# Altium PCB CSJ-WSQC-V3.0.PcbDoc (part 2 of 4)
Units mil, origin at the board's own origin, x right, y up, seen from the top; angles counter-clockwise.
Board outline 5060 x 7131.55 mil, 4 copper layers (Top Layer, InternalPlane1, InternalPlane2, Bottom Layer); 390 components, 277 nets, 1183 pads, 601 vias.
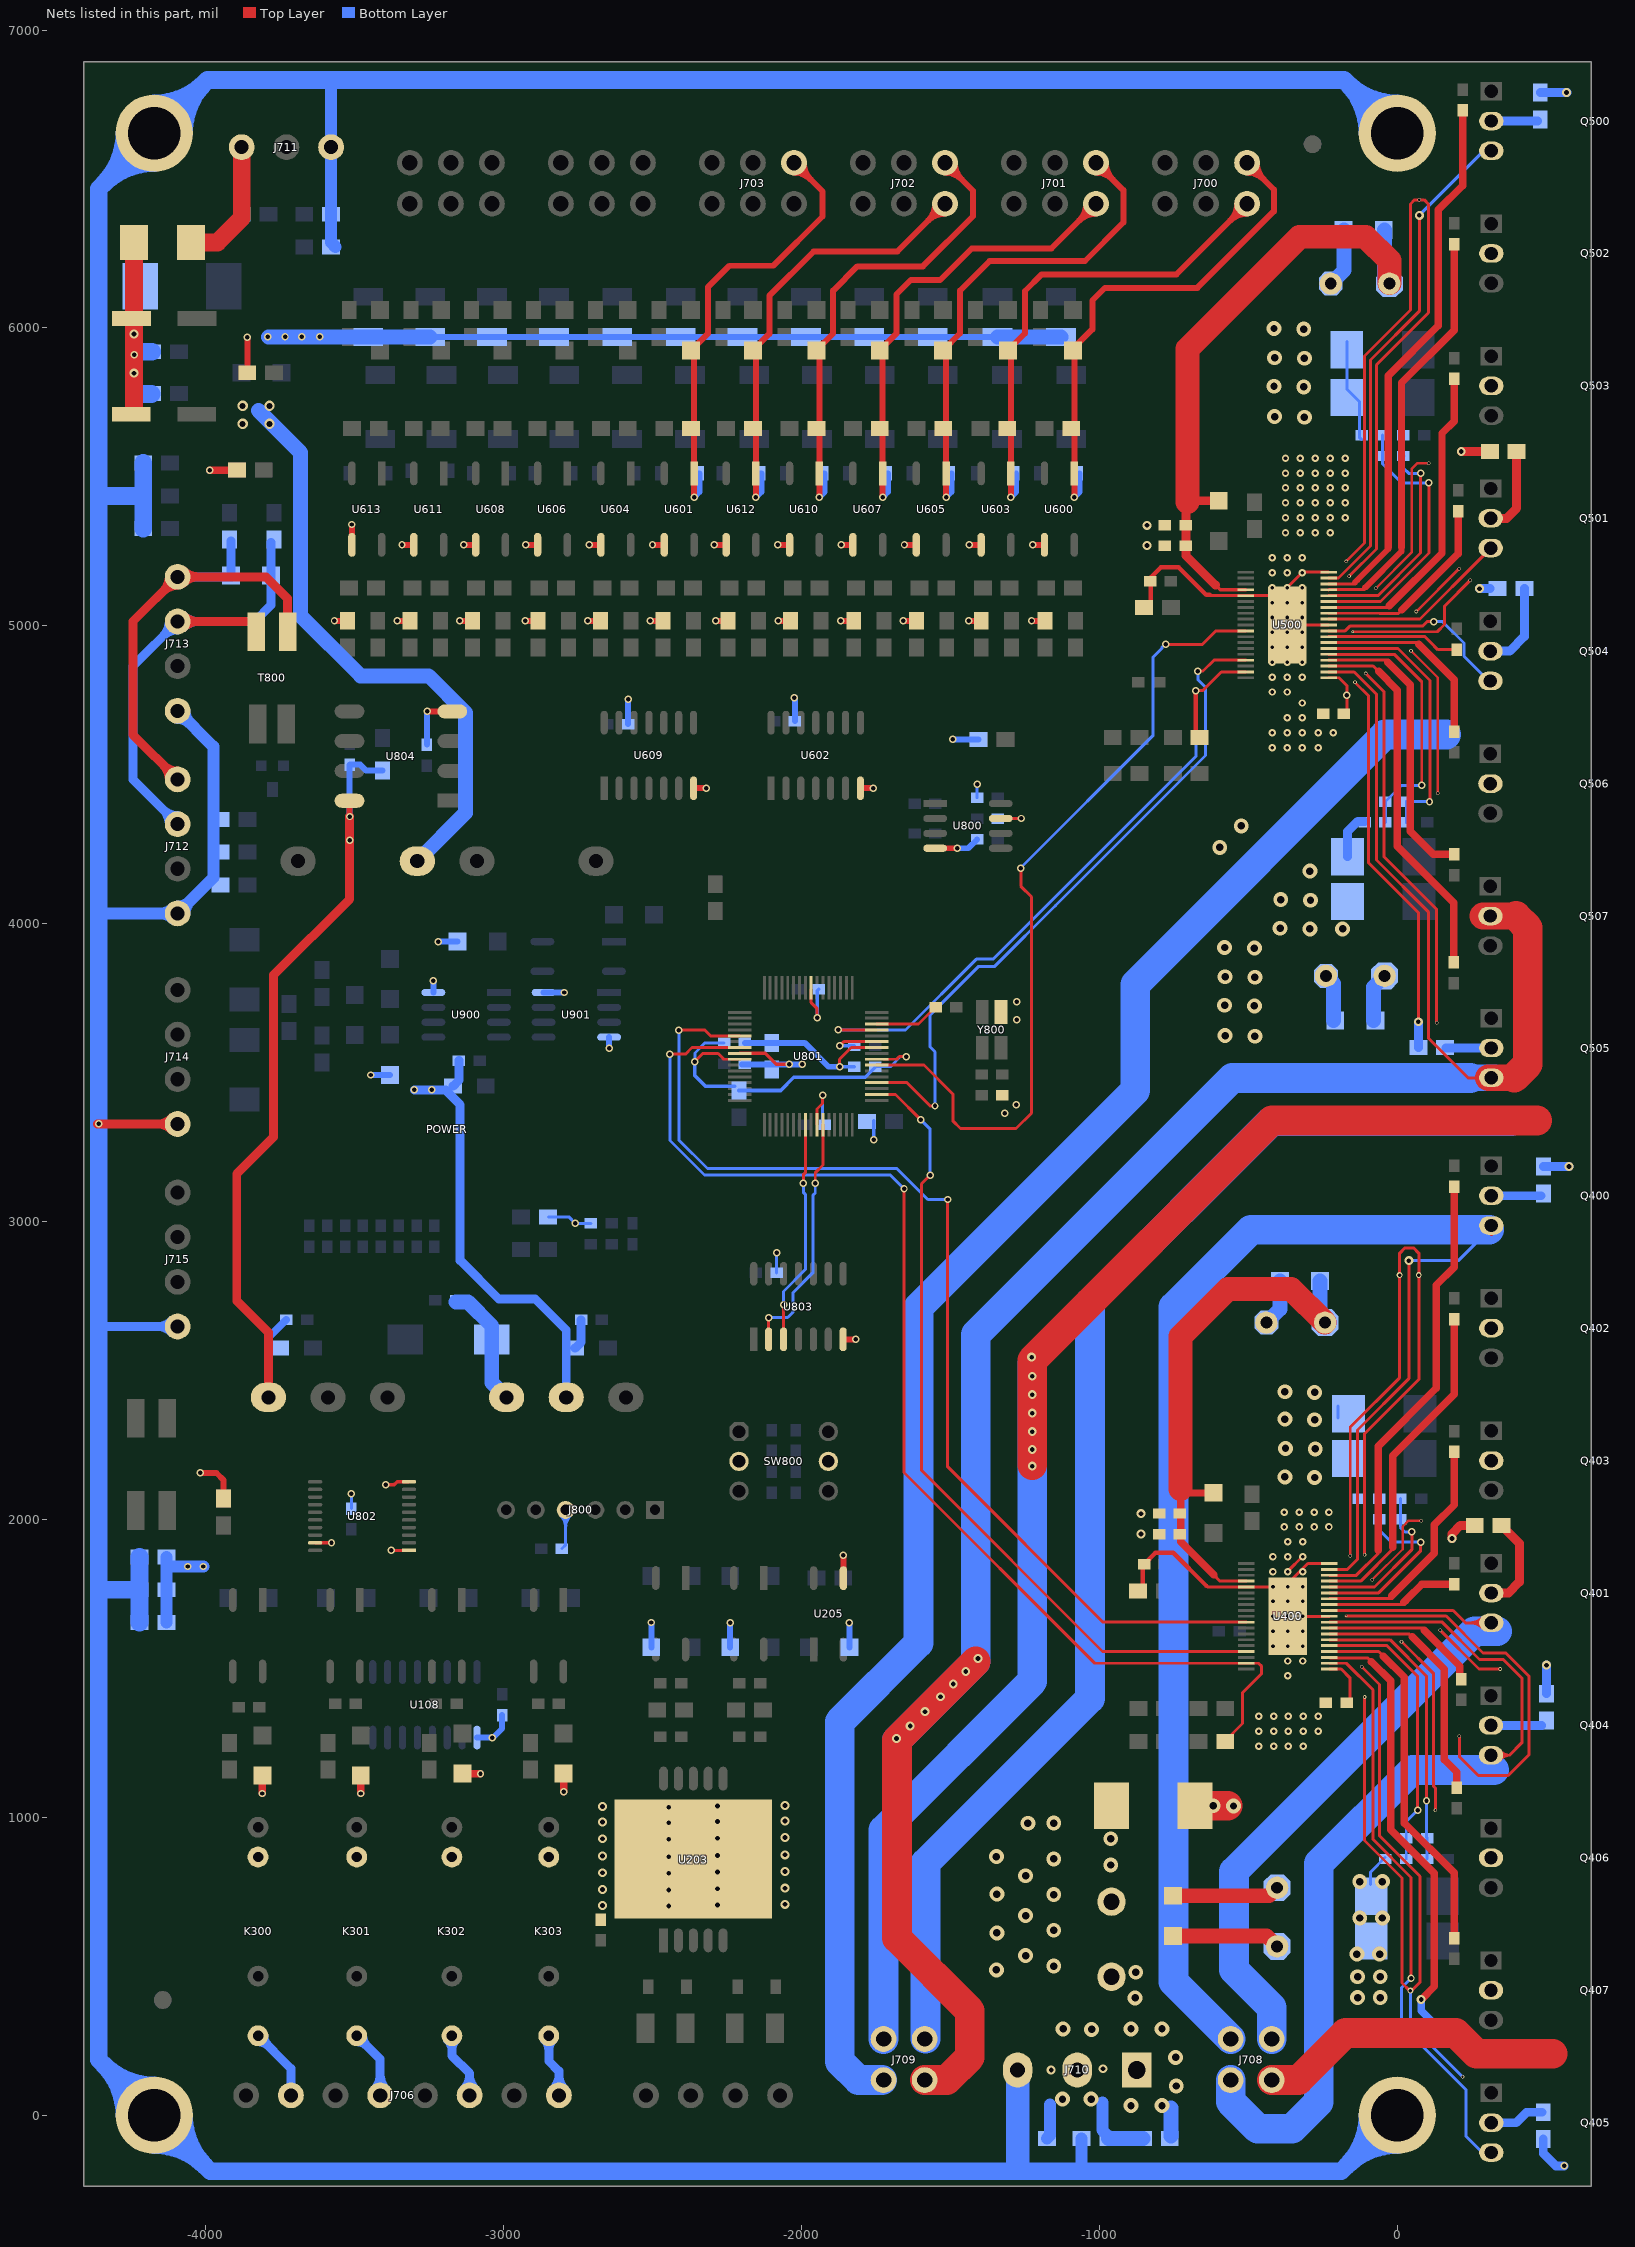
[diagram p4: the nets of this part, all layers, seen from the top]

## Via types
v1: diameter 25, hole 15, Top Layer to Bottom Layer, 303 vias
v2: diameter 25, hole 12, Top Layer to Bottom Layer, 94 vias
v3: diameter 50, hole 25, Top Layer to Bottom Layer, 71 vias
v4: diameter 30, hole 16, Top Layer to Bottom Layer, 71 vias
v5: diameter 12, hole 8, Top Layer to Bottom Layer, 25 vias
v6: diameter 25, hole 12, Top Layer to Bottom Layer, tented both sides, 24 vias
v7: diameter 35, hole 20, Top Layer to Bottom Layer, 7 vias
v8: diameter 20, hole 12, Top Layer to Bottom Layer, 3 vias
v9: diameter 8, hole 5, Top Layer to Bottom Layer, 2 vias
v10: diameter 35, hole 25, Top Layer to Bottom Layer, 1 vias

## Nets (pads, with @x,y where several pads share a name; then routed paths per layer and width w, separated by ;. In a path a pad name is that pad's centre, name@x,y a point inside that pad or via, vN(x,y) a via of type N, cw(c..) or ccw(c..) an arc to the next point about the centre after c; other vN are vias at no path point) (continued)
485P1: C116.1 C117.1 C119.1 C120.1 D105.1 POWER.6 R901.2 R902.1 U900.8 U901.8 | length 1958.1
  Top Layer w20: v1(-4018,2156) -3964,2156 -3940,2132 D105.1@-3940,2070
  Bottom Layer w20: v1(-3446,3492) R902.1@-3382,3492 ; U900.8@-3236,3769 v1(-3236,3808) ; v1(-3219,3940) R901.2@-3155,3940 ; U901.8@-2866,3769 v1(-2797,3769)
  Bottom Layer w30: v1(-3300,3442) -3196,3442 -3146,3392 -3146,2870 -3016,2740 -2894,2740 -2790,2636 POWER.6@-2790,2410 ; C120.1@-3170,3455 -3150,3475 C119.1@-3150,3540 ; C117.1@-2760,2575 -2740,2595 C116.1@-2740,2670
  other v1: -3242,3442
+5V: C108.1 C109.1 C808.1 C816.1 D101.1 POWER.10 U804.8 | length 2871.6
  Top Layer w20: v1(-3517.45,4359.73) U804.8@-3517.45,4412.73
  Top Layer w25: v1(-3986,5522.44) D101.1@-3895.38,5522.44
  Top Layer w30: POWER.10@-3790,2410 -3790,2628 -3896,2734 -3896,3160 -3772,3284 -3772,3828 -3517.45,4082.55 v1(-3517.45,4359.73)
  Bottom Layer w20: v1(-3517.45,4359.73) -3517.45,4532.73 C808.1@-3516.45,4533.73 -3481.45,4533.73 -3461.45,4513.73 C816.1@-3406.45,4513.73
  Bottom Layer w25: POWER.10@-3790,2410 -3790,2610 C108.1@-3730,2670
  other v1: -3517.45,4280
+24V: C101.1 C102.1 C104.1 C105.1 C201.1 C304.1 D100.2 D103.1 F100.2 K300.3 K301.3 K302.3 K303.3 POWER.2 R200.1 R204.1 R221.2 R300.1 R305.1 R313.1 R319.1 R700.2 R701.2 R702.2 R703.2 R704.2 R705.2 R706.2 R707.2 R708.2 R709.2 R710.2 R711.2 U108.9 U203.11 | length 6446.9
  Top Layer w20: D103.1@-3860.73,5849.38 v1(-3860.73,5968.73)
  Top Layer w25: v1(-3810,1080) R319.1@-3810,1140 ; v1(-3480,1080) R313.1@-3480,1140 ; R305.1@-3137.78,1146.73 v1(-3077.78,1146.73) ; v1(-2798,1086) R300.1@-2798,1146
  Top Layer w60: C102.1@-4240.79,5719.21 v4(-4240.79,5848) F100.2@-4240.79,6286.73
  Bottom Layer w20: R711.2@-3246.72,5969.73 R704.2@-3038.99,5969.73 R710.2@-2831.27,5969.73 R703.2@-2618.54,5969.73 R709.2@-2405.81,5969.73 R702.2@-2198.08,5969.73 R708.2@-1985.36,5969.73 R701.2@-1772.63,5969.73 R707.2@-1559.9,5969.73 R700.2@-1342.18,5969.73 ; U108.9@-3089.45,1267.73 v1(-3038,1267.73) ; v1@-3035.45,1267.73 -3005.45,1297.73 C304.1@-3005.45,1342.73 ; R200.1@-2504.45,1570.73 v1@-2504.45,1653.55 ; R204.1@-2239.45,1570.73 v1(-2239.45,1653.55) ; R221.2@-1839.45,1570.73 v1(-1839.45,1653.55)
  Bottom Layer w50: -3823,5723 -3682,5582 -3682,5034 -3480,4832 -3252,4832 -3128,4708 -3128,4372 POWER.2@-3290,4210 ; v1@-3790,5969.73 R705.2@-3454.45,5969.73 R711.2@-3246.72,5969.73 ; R700.2@-1342.18,5969.73 R706.2@-1129.45,5969.73
  Bottom Layer w60: D100.2@-4240.79,6133.07 v4(-4240.79,5980) v4(-4240.79,5848) -4240.79,5778 C105.1@-4182,5778 ; v1@-4236.79,5920 C104.1@-4180,5920
  other v1: -2504,1654 -4240.79,5910 -3792,5970 -3734,5969.73 -3678,5970 -3618,5970
  other v4: -2446,702 -2668,704 -2282,706 -2056,708 -2446,756 -2668,758 -2282,760 -2056,762 -2446,812 -2668,814 -2282,816 -2056,818 -2446,868 -2668,870 -2282,872 -2056,874 -2446,926 -2668,928 -2282,930 -2056,932 -2446,982 -2668,984 -2282,986 -2056,988 -2446,1034 -2668,1036 -2282,1038 -2056,1040
  other v7: -3876,5678 -3786,5678 -3876,5738 -3786,5738
+24VIN: C100.1 F100.1 J711.3 | length 667.1
  Top Layer w60: F100.1@-4049.45,6286.73 -3961.27,6286.73 -3879.45,6368.55 J711.3@-3879.45,6606.73
  Bottom Layer w50: C100.1@-3879.45,6381.73 J711.3@-3879.45,6606.73
+48V: C400.1 C401.1 C402.1 C403.1 C404.1 C405.1 C407.2 C410.1 C411.1 C413.1 C414.1 C500.1 C501.1 C502.1 C503.1 C504.1 C505.1 C507.2 C510.1 C511.1 C513.1 C514.1 D104.2 pad.@-26.6,6148.73 pad.@-42.6,3824.73 pad.@-242.6,2660.73 pad.@-403.45,763.58 Q400.2 Q401.2 Q404.2 Q405.2 Q500.2 Q501.2 Q504.2 Q505.2 R111.2 U400.4 U500.4 | length 6283.8
  Top Layer w10: -616,1814 -594.84,1792.84 U400.4@-506.62,1792.84
  Top Layer w12: -619.15,5145.15 -611,5137 -594.84,5120.84 U500.4@-508.62,5120.84
  Top Layer w20: C407.2@-608.45,2089.73 C407.2@-607.45,2089.73 ; C401.1@-243.45,2660.73 C401.1@-242.6,2660.73
  Top Layer w25: -727.45,2102 -727.45,2088.73 ; -616,1814 -616.49,1814 -727.45,1924.96 -727.45,2088.73 ; C407.2@-608.45,2088.73 -727.45,2088.73 ; C401.1@-243.02,2660.31 C401.1@-242.6,2660.73
  Top Layer w30: -709.45,5415.45 -709.45,5235.45 -611,5137 ; -709.45,5440.55 -704,5446 ; -688.63,5419.73 C507.2@-599.45,5419.73 ; C513.1@-26.6,6133.58 C513.1@-26.6,6148.73 C513.1@-26.6,6150 ; Q401.2@315.55,1752.96 372.78,1752.96 410,1790.18 410,1919.28 C400.1@354.55,1974.73 ; Q501.2@315.55,5360.85 366.67,5360.85 400.55,5394.73 C500.1@400.55,5584.73
  Top Layer w50: C414.1@-753.45,736.73 -430.3,736.73 C413.1@-403.45,763.58
  Top Layer w80: -727.45,2102 -727.45,2614.55 -568,2774 -356.71,2774 C401.1@-243.45,2660.73 ; -704,5415.45 -704,5446 -704,5930 -328,6306 -106,6306 -26.6,6226.6 C513.1@-26.6,6150
  Bottom Layer w30: C510.1@162.66,3582.62 Q505.2@315.55,3582.62 ; Q504.2@312.55,4914.73 376.73,4914.73 426.55,4964.55 C505.1@426.55,5124.73 ; Q405.2@315.55,-25.27 398.73,-25.27 434,10 C410.1@486,10 ; Q404.2@315.55,1308.41 C411.1@484.23,1308.41 ; Q400.2@315.55,3086.64 C405.1@482.46,3086.64 ; Q500.2@315.55,6694.53 C511.1@470.35,6694.53
  Bottom Layer w50: C504.1@-259.45,2800.73 -259.45,2677.58 C401.1@-242.6,2660.73 ; C404.1@-79.45,3674.73 -79.45,3787.88 C501.1@-42.6,3824.73 ; C514.1@-43.45,6328.73 -43.45,6165.58 C513.1@-26.6,6148.73
  other v3: -1346,488 -1153.45,500.73 -1248,536 -1344,612 -1153.45,620.73 -1248,670 -1153.45,740.73 -1344,742 -1248,804 -962,840 -1153.45,860.73 -1346,868 -962,928 -1240,980 -1153.45,980.73
+48VIN: C114.1 J710.1 R111.1 | length 94
  Bottom Layer w50: C114.1@-760,-70 -760,24
  other v3: -894,32 -790,32 -742,98 -744,194 -894,290 -790,290 -880,394 -878,480
A1HS: R400.1 U400.36 | length 1530.9
  Top Layer w10: U400.36@-228.27,1812.53 -137.47,1812.53 -64,1886 -64,1896
  Top Layer w25: -64,1896 -64,2246 130,2440 130,2786 190.55,2846.55 R400.1@190.55,3116.73
A1LS: R402.1 U400.35 | length 1124.3
  Top Layer w10: U400.35@-228.27,1792.84 -136,1792.84 ; -129.16,1792.84 -136,1792.84 ; -10,1906 -123.16,1792.84 -136,1792.84
  Top Layer w25: -16,1906 -16,2214 190.55,2420.55 R402.1@190.55,2672.73
A2HS: R401.2 U400.31 | length 460.7
  Top Layer w10: U400.31@-228.27,1714.1 26.1,1714.1 35,1723
  Top Layer w25: 22,1722 35,1735 82.73,1782.73 R401.2@190.55,1782.73
A2LS: R403.2 U400.32 | length 804.9
  Top Layer w10: U400.32@-228.27,1733.79 -18.21,1733.79 0,1752
  Top Layer w25: -18,1744 124,1886 124,1982 190.55,2048.55 R403.2@190.55,2226.73
A3HS: R500.1 U500.36 | length 1833.6
  Top Layer w10: U500.36@-230.27,5140.53 -141.47,5140.53 -133.82,5148.18
  Top Layer w20: -142,5146 -133.82,5154.18 -30,5258 -30,5264
  Top Layer w25: -30,5264 -30,5840 138,6008 138,6396 220,6478 R500.1@220,6730
A3LS: R502.1 U500.35 | length 1402.8
  Top Layer w10: U500.35@-230.27,5120.84 -229.52,5121.6 -110.4,5121.6 -106,5126
  Top Layer w20: -108,5128 14,5250 14,5264
  Top Layer w25: 14,5264 14,5816 190.55,5992.55 R502.1@190.55,6280.73
A4HS: R501.2 U500.31 | length 660.5
  Top Layer w10: U500.31@-230.27,5042.1 -60,5042.1 -59.46,5041.56 -16.38,5041.56 3.56,5041.56 15,5053
  Top Layer w25: 15,5053 204.55,5242.55 R501.2@204.55,5384.73
A4LS: R503.2 U500.32 | length 1066.5
  Top Layer w10: U500.32@-230.27,5061.79 -129.45,5061.79 ; -124.19,5061.79 -129.45,5061.79 ; -26.94,5067.06 -32.21,5061.79 -129.45,5061.79
  Top Layer w20: R503.2@190.55,5824.73 R503.2@190.55,5828.73
  Top Layer w25: -26.94,5067.06 150,5244 150,5646 190.55,5686.55 190.55,5824.73 R503.2@186.55,5824.73
AGND: C813.2 C814.2 R110.2 U801.42 | length 561.6
  Top Layer w10: v1(-1872.45,3519.73) -1872.45,3544.73 -1832.92,3584.26 U801.42@-1753.04,3584.26
  Bottom Layer w12: v1(-1872.45,3519.73) C813.2@-1822.45,3519.73
  Bottom Layer w20: C814.2@-2190,3600 R110.2@-2100,3600 -1989.76,3600 -1909.5,3519.73 v1(-1872.45,3519.73)
AISENN_1: C415.1 R415.1 U400.33 | length 657.3
  Top Layer w10: U400.33@-228.27,1753.47 -62.53,1753.47 78.55,1894.55 v1@78.55,1926
  Bottom Layer w10: R415.1@-60,2070 C415.1@-60,2000 -60,1964 -20,1924 v1(78,1924)
AISENN_2: C515.1 R515.1 U500.33 | length 910.6
  Top Layer w10: U500.33@-230.27,5081.47 -56.53,5081.47 106,5244 106,5474 v1@100,5480
  Bottom Layer w10: R515.1@-50,5640 C515.1@-50,5570 -50,5544 14,5480 v1@96,5480
  other v1: 106,5480
AISENP_1: C415.2 R417.1 U400.34 | length 536.3
  Top Layer w10: U400.34@-228.27,1773.16 -76.84,1773.16 48.55,1898.55 48.55,1914 ; 48.55,1906.55 48.55,1914 ; v1@48.55,1958 48.55,1914
  Bottom Layer w10: R417.1@10,2070 C415.2@10,2000 10,1974 26,1958 v1(48,1958)
AISENP_2: C515.2 R517.1 U500.34 | length 803.4
  Top Layer w10: U500.34@-230.27,5101.16 -230.23,5101.2 -64.8,5101.2 78,5244 78,5506 v1@72,5512
  Bottom Layer w10: R517.1@20,5640 C515.2@20,5570 ; C515.2@22,5570 C515.2@20,5570 ; v1@66,5512 38,5512 20,5530 C515.2@20,5570
  other v1: 78,5512
AOUT1: J708.1 Q400.3 Q402.2 U400.37 | length 5396.1
  Top Layer w10: -197.29,1832.21 U400.37@-228.27,1832.21 -167.79,1832.21 -134,1866 -134,2300 38.55,2472.55 v4(38.55,2868.73) ; Q400.3@315.55,2955.73 Q400.3@315.55,2986.64
  Bottom Layer w10: 172.55,2868.73 v4(38.55,2868.73) 204.73,2868.73 Q400.3@308.73,2972.73
  Bottom Layer w100: J708.1@-559.45,255.71 -751.45,447.71 -751.45,2712.73 -491.45,2972.73 Q400.3@308.73,2972.73
AOUT2: J708.2 Q401.3 Q403.2 U400.30 | length 2552.4
  Top Layer w10: U400.30@-228.27,1694.42 187.58,1694.42 229.04,1652.96 Q401.3@315.55,1652.96 ; Q401.3@287.17,1634.58 ccw(c242.78,1590.19) 242.78,1652.96 ccw(c242.78,1715.73) Q401.3@287.17,1671.35 ; Q401.3@294.24,1641.65 ccw(c266.92,1614.34) 266.92,1652.96 ccw(c266.93,1691.59) Q401.3@294.24,1664.28
  Bottom Layer w100: J708.2@-421.65,255.71 -421.65,361.65 -548,488 -548,818 258.73,1624.73 Q401.3@335.32,1624.73
AOUT3: J709.1 Q500.3 Q502.2 U500.37 | length 6566.3
  Top Layer w10: U500.37@-230.27,5160.21 -197.26,5160.21 -90,5267.47 -90,5892 74,6056 v4@74,6366 ; v4@74,6366 80,6372 v4(74,6378) v4@74,6366
  Top Layer w100: v4@-1225.45,2182.73 -1225.45,2534.73 -421.02,3339.16 468.54,3339.16
  Bottom Layer w10: v4(74,6378) 290.53,6594.53 Q500.3@315.55,6594.53
  Bottom Layer w100: J709.1@-1724.45,255.71 -1724.45,957.73 -1225.45,1456.73 -1225.45,2524.73
  other v4: -1225.45,2178.73 -1225.45,2234.73 -1225.45,2294.73 -1225.45,2356.73 -1225.45,2418.73 -1225.45,2480.73 -1227.45,2544.73
AOUT4: J709.2 Q501.3 Q503.2 U500.30 | length 4999.6
  Top Layer w10: U500.30@-230.27,5022.42 76.42,5022.42 288.85,5234.85 Q501.3@288.85,5260.85
  Bottom Layer w100: J709.2@-1583.45,256.73 -1583.45,846.73 -1031.45,1398.73 -1031.45,2728.73 -423.45,3336.73 382.55,3336.73
AVCC: C813.1 C814.1 L100.2 U801.9 U801.40 | length 1200.4
  Top Layer w10: v1@-2360,3536 -2331.94,3564.06 -2279.94,3564.06 -2270.48,3554.59 -2260.78,3544.89 U801.9@-2206.86,3544.89 ; U801.40@-1723.04,3544.89 -1680.46,3544.89 -1671.62,3553.73 v1(-1648.45,3553.73)
  Bottom Layer w10: v1(-2358,3536) -2358,3538 -2358,3566 -2324,3600 C814.1@-2260,3600 ; C813.1@-1752.45,3519.73 -1701.62,3519.73 -1667.62,3553.73 v1(-1648.45,3553.73)
  Bottom Layer w12: v1@-2358,3538 -2360,3536 -2358,3534 -2358,3490.11 -2322.62,3454.73 L100.2@-2224.73,3454.73 ; L100.2@-2210,3440 -2070,3440 -2026,3484 -1786,3484 -1752.45,3517.55 C813.1@-1752.45,3519.73
B1HS: R407.1 U400.27 | length 535.6
  Top Layer w10: U400.27@-228.27,1635.36 92,1635.36
  Top Layer w25: 90,1628 210,1508 210,1468 R407.1@214,1464
B1LS: R411.1 U400.26 | length 846.2
  Top Layer w10: U400.26@-228.27,1615.68 40.32,1615.68 47,1609
  Top Layer w25: 50,1606 158,1498 158,1194 200,1152 R411.1@200,1100
B2HS: R408.2 U400.22 | length 1581.9
  Top Layer w10: U400.22@-228.27,1536.94 -226.59,1535.25 -99.25,1535.25 -87,1523
  Top Layer w25: -87,1523 -22,1458 -22,958 124,812 124,432 v4(80,388)
  Bottom Layer w25: v4(80,388) 80,350 R408.2@190.5,239.5
B2LS: R412.2 U400.23 | length 1232.4
  Top Layer w10: U400.23@-228.27,1556.62 -62.62,1556.62 -47,1541
  Top Layer w25: -47,1541 24,1470 24,980 190.55,813.45 R412.2@190.55,594.73
B3HS: R507.1 U500.27 | length 461.1
  Top Layer w10: U500.27@-230.27,4963.36 -167.45,4963.36 ; -180.27,4963.36 -167.45,4963.36 ; R507.1@200,4920 136,4920 111.27,4944.73 106,4950 92.64,4963.36 -167.45,4963.36
B3LS: R511.1 U500.26 | length 651.3
  Top Layer w10: U500.26@-230.27,4943.68 32,4943.68 ; 38.89,4943.68 32,4943.68 ; 72,4943.68 32,4943.68
  Top Layer w25: 72.14,4937.86 190.55,4819.45 R511.1@190.55,4644.73
B4HS: R508.2 U500.22 | length 1274.9
  Top Layer w10: U500.22@-230.27,4864.94 -80.94,4864.94 -63.01,4847.01 -50,4834
  Top Layer w25: -63.01,4847.01 0,4784 0,4260 190,4070 R508.2@190,3870
B4LS: R512.2 U500.23 | length 979.1
  Top Layer w10: U500.23@-230.27,4884.62 -38.62,4884.62 -32,4878
  Top Layer w25: -32,4878 44,4802 44,4310 121.27,4232.73 R512.2@190.55,4232.73
BEMF_1: C412.1 U400.20 | length 164.8
  Top Layer w10: U400.20@-228.27,1497.57 -188.28,1497.57 -159.45,1468.73 -159.45,1436.73 C412.1@-159.45,1384.73
BEMF_2: C512.1 U500.20 | length 170.5
  Top Layer w10: U500.20@-230.27,4825.57 -195.57,4825.57 -169.45,4799.45 v1(-169.45,4766.73) -169.45,4714.73 C512.1@-179.45,4704.73
BISENN_1: C416.1 R416.1 U400.24 | length 968.4
  Top Layer w10: U400.24@-228.27,1576.31 -34.31,1576.31 68,1474 v1(68,1024)
  Bottom Layer w10: R416.1@30,860 C416.1@30,930 30,986 v1(68,1024)
BISENN_2: C516.1 R516.1 U500.24 | length 916.9
  Top Layer w10: U500.24@-230.27,4904.31 -10.31,4904.31 82,4812 v1(82,4464)
  Bottom Layer w10: R516.1@-43.45,4344.73 R516.1@-40,4344.73 ; R516.1@-40,4340 R516.1@-40,4344.73 ; R516.1@-39.45,4344.73 R516.1@-40,4344.73 ; v1(82,4464) 14,4464 C516.1@-40,4410 R516.1@-40,4344.73
BISENP_1: C416.2 R418.1 U400.25 | length 993.8
  Top Layer w10: U400.25@-228.27,1595.99 -23.99,1595.99 98,1474 v1(98,1056)
  Bottom Layer w10: v1(98,1056) 98,932 C416.2@100,930 ; R418.1@100,860 C416.2@100,930 ; C416.2@100,932.15 C416.2@100,930
BISENP_2: C516.2 R518.1 U500.25 | length 939.8
  Top Layer w10: U500.25@-230.27,4923.99 2.01,4923.99 110,4816 110,4412 v1(108,4410)
  Bottom Layer w10: R518.1@30,4340 C516.2@30,4410 v1(108,4410)
BOUT1: J708.3 Q404.3 Q406.2 U400.28 | length 3161.9
  Top Layer w10: U400.28@-228.27,1655.05 44.55,1655.05 ; 66.55,1655.05 44.55,1655.05 ; Q404.3@314.55,1208.41 376.41,1208.41 ; Q404.3@337.37,1198.84 cw(c356.46,1184.59) 356.46,1208.41 cw(c356.46,1232.22) Q404.3@337.37,1217.98 ; Q404.3@345.39,1192.85 cw(c376.4,1169.7) 376.4,1208.41 ; Q404.3@345.39,1223.96 ccw(c376.4,1247.11) 376.4,1208.41 ; 44.55,1655.05 150.95,1655.05 276,1530 356,1530 418,1468 418,1250 376.41,1208.41
  Bottom Layer w100: J708.3@-559.45,117.91 -559.45,45.45 -468.73,-45.27 -353.45,-45.27 -263.45,44.73 -263.45,844.55 50.73,1158.73 324.55,1158.73
BOUT2: J708.4 Q405.3 Q407.2 U400.21 | length 2983.6
  Top Layer w10: U400.21@-228.27,1517.25 -171.25,1517.25 -82,1428 -82,926 46,798 v1(46,460)
  Top Layer w100: J708.4@-421.65,117.91 -332.09,117.91 -174,276 196,276 266,206 522,206
  Bottom Layer w10: v1(46,460) 14,428 14,302 230,86 230,-70 285.27,-125.27 Q405.3@315.55,-125.27
BOUT3: J709.3 Q504.3 Q506.2 U500.28 | length 6244.6
  Top Layer w10: U500.28@-229.96,4982.73 U500.28@-230.27,4983.05 -174.95,4983.05 -159.27,4998.73 84.73,4998.73 100,5014 v1(122,5014)
  Bottom Layer w10: v1(122,5014) 152,5014 224,4942 224,4898 Q504.3@307.27,4814.73
  Bottom Layer w100: J709.3@-1729.92,117.91 -1808.63,117.91 -1871.45,180.73 -1871.45,1320.73 -1607.45,1584.73 -1607.45,2712.55 -880,3440 -880,3796 -41.27,4634.73 164.55,4634.73
BOUT4: J709.4 pad.@312.55,4025.62 Q505.3 Q507.2 U500.21 | length 7739.1
  Top Layer w10: U500.21@-230.27,4845.25 -144.73,4845.25 -70,4770.53 -70,4214 104,4040 104,3616 237.38,3482.62 Q505.3@302,3482.62
  Top Layer w90: Q507.2@288,4025.62 398.38,4025.62 ; Q505.3@306,3482.62 392.44,3482.62
  Top Layer w100: J709.4@-1586.65,117.91 -1512.27,117.91 -1435.45,194.73 -1435.45,350.73 -1679.45,594.73 -1679.45,1258.73 v4(-1490.76,1447.42) v4(-1448.83,1489.35) v4@-1415.45,1522.73 ; 392.44,3482.62 438,3528.18 438,3986 398.38,4025.62
  Bottom Layer w90: 246,3482 Q505.3@315.55,3482.62 Q505.3@328,3482.62
  Bottom Layer w100: v4@-1679.45,1258.73 v4(-1533.45,1404.73) -1415.45,1522.73 -1415.45,2620.55 -554,3482 246,3482
  other v4: -1681.45,1264.73 -1635.45,1306.73 -1585.45,1354.73 -1407.45,1532.73
CAN1RXD: U801.27 U803.2 | length 833.6
  Top Layer w10: U803.2@-2110.45,2604.73 v1(-2110.45,2677.55) ; v1(-1954,3128) -1954,3164 -1928.24,3189.76 U801.27@-1928.24,3325.32
  Bottom Layer w10: v1(-2110.45,2677.55) -2046.45,2677.55 -2028,2696 -2028,2762 -1962,2828 -1962,3088 -1954,3096 v1(-1954,3128)
CAN1TXD: U801.24 U803.3 | length 756.5
  Top Layer w10: U803.3@-2060.45,2604.73 v1(-2060.45,2720) ; v1(-1994,3128) -1994,3157.29 -1987.29,3164 U801.24@-1987.29,3325.32
  Bottom Layer w10: v1(-2060.45,2720) -2060.45,2765.55 -1987.29,2838.71 -1987.29,3091.29 -1994,3098 v1(-1994,3128)
CANH: C805.2 J712.2 J713.2 R820.1 T800.3 | length 2562.4
  Top Layer w30: J713.2@-4094.45,5014.37 -4026.11,5014.37 ; J713.2@-4074.43,4994.35 cw(c-4026.11,4946.03) -4026.11,5014.37 ; J713.2@-4074.43,5034.39 ccw(c-4026.11,5082.71) -4026.11,5014.37 ; -3864.37,5014.37 -4026.11,5014.37
  Bottom Layer w30: J712.2@-4122.76,4334.37 ccw(c-4191.09,4334.37) -4142.77,4382.69 ; J712.2@-4094.45,4334.37 -4244.45,4484.37 ; J712.2@-4094.45,4362.68 cw(c-4094.45,4431.02) -4142.77,4382.69 ; -3997.09,5014.37 J713.2@-4094.45,5014.37 ; C805.2@-3780.73,5279.38 R820.1@-3780.73,5169.38 -3780.73,5070 -3836.36,5014.37 J713.2@-4094.45,5014.37 ; -4244.45,4484.37 -4142.77,4382.69 ; -4244.45,4484.37 -4244.45,4864.37 J713.2@-4094.45,5014.37 ; -4142.77,4966.05 cw(c-4094.45,4917.72) J713.2@-4094.45,4986.06 ; -4142.77,4966.05 ccw(c-4191.09,5014.37) -4122.76,5014.37 cw(c-4191.09,5014.37) -4142.77,4966.05 ; -4142.77,4966.05 cw(c-4094.45,4917.72) J713.2@-4094.45,4986.06 ; -4142.77,4966.05 J713.2@-4094.45,5014.37 ; J713.2@-4094.45,4986.06 J713.2@-4094.45,5014.37 ; -4026.11,5014.37 cw(c-4026.11,5082.71) -4074.43,5034.39 ccw(c-4026.11,5082.71) -4026.11,5014.37 ; -4026.11,5014.37 ccw(c-4026.11,4946.03) -4074.43,4994.35 cw(c-4026.11,4946.03) -4026.11,5014.37
CANL: C806.1 J712.1 J713.1 R820.2 T800.4 | length 2344.3
  Top Layer w30: J712.1@-4122.76,4484.37 ccw(c-4191.09,4484.37) -4142.77,4532.69 ; J712.1@-4094.45,4484.37 -4244.45,4634.37 ; J712.1@-4094.45,4512.68 cw(c-4094.45,4581.02) -4142.77,4532.69 ; J713.1@-4074.43,5144.35 cw(c-4026.11,5096.03) -4026.11,5164.37 ; J713.1@-4074.43,5184.39 ccw(c-4026.11,5232.71) -4026.11,5164.37 ; T800.4@-3725,4980 -3725,5091 -3798.37,5164.37 -4004,5164.37 ; -4244.45,4634.37 -4244.45,5014.37 J713.1@-4094.45,5164.37 ; -4244.45,4634.37 -4142.77,4532.69 ; -4142.77,5116.05 cw(c-4094.45,5067.72) J713.1@-4094.45,5136.06 ; -4142.77,5116.05 ccw(c-4191.09,5164.37) -4122.76,5164.37 cw(c-4191.09,5164.37) -4142.77,5116.05 ; -4142.77,5116.05 cw(c-4094.45,5067.72) J713.1@-4094.45,5136.06 ; -4142.77,5116.05 J713.1@-4094.45,5164.37 ; J713.1@-4094.45,5136.06 J713.1@-4094.45,5164.37 ; J713.1@-4094.45,5164.37 -3982.09,5164.37 -4004,5164.37 ; -4026.11,5164.37 -4004,5164.37
  Bottom Layer w30: J713.1@-4094.45,5164.37 R820.2@-3916,5164.37 ; R820.2@-3915.73,5169.38 C806.1@-3915.73,5284.38
CLKIN: R813.1 U801.46 | length 221.6
  Top Layer w10: U801.46@-1748.04,3663 -1607,3663 R813.1@-1550,3720
COM5: J706.2 K300.1 | length 321.4
  Bottom Layer w30: K300.1@-3824.45,246.73 cw(c-3824.45,198.45) -3790.31,232.59 cw(c-3756.16,266.73) K300.1@-3804.45,266.73 ; K300.1@-3824.45,266.73 -3714.45,156.73 J706.2@-3714.45,66.73
COM6: J706.4 K301.1 | length 415.8
  Bottom Layer w30: K301.1@-3493.11,246.73 cw(c-3493.11,198.45) -3458.97,232.59 cw(c-3424.83,266.73) K301.1@-3473.11,266.73 ; K301.1@-3493.11,266.73 -3414.45,188.07 J706.4@-3414.45,66.73 ; J706.4@-3434.46,86.75 ccw(c-3482.79,135.07) -3414.45,135.07 ccw(c-3346.11,135.07) J706.4@-3394.43,86.75
COM7: J706.6 K302.1 | length 407.8
  Bottom Layer w30: K302.1@-3187.92,252.59 cw(c-3222.07,218.45) -3173.78,218.45 cw(c-3125.5,218.45) K302.1@-3159.64,252.59 ; K302.1@-3173.78,266.73 -3173.78,199.78 -3114.45,140.45 J706.6@-3114.45,66.73 ; J706.6@-3134.46,86.75 ccw(c-3182.79,135.07) -3114.45,135.07 ccw(c-3046.11,135.07) J706.6@-3094.43,86.75
COM8: J706.8 K303.1 | length 397.3
  Bottom Layer w30: K303.1@-2862.59,252.59 cw(c-2896.73,218.45) -2848.45,218.45 cw(c-2800.16,218.45) K303.1@-2834.31,252.59 ; K303.1@-2848.45,266.73 -2848.45,182 -2814.45,148 J706.8@-2814.45,66.73 ; J706.8@-2834.46,86.75 ccw(c-2882.79,135.07) -2814.45,135.07 ccw(c-2746.11,135.07) J706.8@-2794.43,86.75
CS1: U400.16 U801.34 | length 2728.6
  Top Layer w10: U801.34@-1748.04,3426.78 -1698,3426.78 -1692.78,3426.78 -1684.78,3426.78 v1(-1600,3342) ; v1(-1568,3156) -1597.45,3126.55 -1597.45,2164.73 -989.34,1556.62 U400.16@-506.62,1556.62
  Bottom Layer w10: v1(-1600,3342) -1568,3310 v1(-1568,3156)
CS2: U500.16 U801.36 | length 2302.2
  Top Layer w10: U801.36@-1748.04,3466.15 -1646.15,3466.15 -1568,3388 v1(-1552,3388) ; v1(-670,4848) -652,4848 -615.38,4884.62 U500.16@-508.62,4884.62
  Bottom Layer w10: v1(-1552,3388) -1552,3570 -1568,3586 -1568,3694 -1405.27,3856.73 -1351.45,3856.73 -1144.09,4064.09 ; -1148.09,4060.09 -1144.09,4064.09 ; v1@-669.76,4848 -669.76,4819.76 -644,4794 -644,4564.18 -1144.09,4064.09
DIR_1: U400.11 U801.5 | length 3685.4
  Top Layer w10: v1@-2414,3640.73 v1@-2412,3640.73 ; v1(-2412,3642.73) -2324.73,3642.73 -2305.63,3623.63 U801.5@-2206.86,3623.63 ; v1(-1509.45,3074) -1509.45,2176.73 -987.76,1655.05 U400.11@-506.62,1655.05
  Bottom Layer w10: v1(-2412,3642.73) -2412,3274 -2316,3178 -1680,3178 -1576,3074 v1(-1509.45,3074)
DIR_2: U500.11 U801.39 | length 2747.1
  Top Layer w10: U801.39@-1748.04,3525.21 -1589.21,3525.21 -1492,3428 -1492,3338 -1466,3312 -1280,3312 -1228,3364 -1228,4090 -1264,4126 v1@-1264,4188 ; v1@-776,4938 -654,4938 -608.95,4983.05 U500.11@-508.62,4983.05
  Bottom Layer w10: v1@-1265,4187 -819.45,4632.55 -819.45,4895.6 -789.45,4925.6 -789.45,4929.6
  other v1: -1264,4186 -778,4938
EGND: C107.2 C112.2 C113.2 C115.2 C118.2 J710.3 J711.1 J712.4 J713.4 J714.4 J715.4 pad.@0,0 pad.@0,6653.54 pad.@-4173.23,0 pad.@-4173.23,6653.54 R103.2 R106.1 R107.2 R108.1 R109.2 R112.2 R113.1 R114.2 | length 21592
  Top Layer w30: v1@-4363.64,3327.64 J714.4@-4094.45,3327.64 ; J714.4@-4114.46,3307.62 ccw(c-4162.79,3259.3) -4162.79,3327.64 ccw(c-4162.79,3395.98) J714.4@-4114.46,3347.65
  Bottom Layer w30: -4357.81,2647.64 J715.4@-4094.45,2647.64 ; J715.4@-4114.46,2627.62 ccw(c-4162.79,2579.3) -4162.79,2647.64 ccw(c-4162.79,2715.98) J715.4@-4114.46,2667.65
  Bottom Layer w40: -4359.08,4034.37 J712.4@-4094.45,4034.37 ; J712.4@-4110.93,4050.85 cw(c-4150.72,4090.64) -4150.72,4034.37 cw(c-4150.72,3978.1) -4110.93,4017.89 J712.4@-4094.45,4034.37 ; J712.4@-4094.45,4057.68 ccw(c-4094.45,4113.95) -4054.66,4074.16 ccw(c-4014.87,4034.37) J712.4@-4071.14,4034.37 ; J713.4@-4094.45,4691.06 cw(c-4094.45,4634.8) -4054.66,4674.58 ; -3579.45,6832 J711.1@-3579.45,6606.73 C107.2@-3579.45,6381.73 -3579.45,6286.73 R103.2@-3564.45,6271.73 ; -1060,-178.27 C115.2@-1060,-78 ; J712.4@-4094.45,4034.37 -3974.45,4154.37 -3974.45,4594.37 J713.4@-4094.45,4714.37 ; J713.4@-4094.45,4714.37 -4054.66,4674.58 ; J713.4@-4094.45,4714.37 -4071.14,4714.37 ccw(c-4014.87,4714.37) -4054.66,4674.58
  Bottom Layer w60: -4357.45,5436 R106.1@-4210,5436 ; -4347.45,1764 C113.2@-4222,1764 ; pad.@-4273.23,0 ccw(c-4514.65,0) -4343.94,170.71 ccw(c-4173.23,341.42) pad.@-4173.23,100 ; pad.@-4273.23,6653.54 cw(c-4514.65,6653.54) -4343.94,6482.83 cw(c-4173.23,6312.12) pad.@-4173.23,6553.54 ; R108.1@-4222,1654 C113.2@-4222,1764 ; R109.2@-4222,1874 C113.2@-4222,1764 ; R107.2@-4210,5326 R106.1@-4210,5436 ; C112.2@-4210,5546 R106.1@-4210,5436 ; pad.@-4173.23,-100 cw(c-4173.23,-341.42) -4002.52,-170.71 cw(c-3831.81,0) pad.@-4073.23,0 ; pad.@-4173.23,6753.54 ccw(c-4173.23,6994.97) -4002.52,6824.25 ccw(c-3831.81,6653.54) pad.@-4073.23,6653.54 ; pad.@-100,0 cw(c-341.42,0) -170.71,-170.71 cw(c0,-341.42) pad.@0,-100 ; pad.@-100,6653.54 ccw(c-341.42,6653.54) -170.71,6824.25 ccw(c0,6994.97) pad.@0,6753.54 ; pad.@0,0 -188,-188 -3985.23,-188 pad.@-4173.23,0 -4359.45,186.22 -4359.45,6467.32 pad.@-4173.23,6653.54 -3994.77,6832 -3579.45,6832 -178.46,6832 pad.@0,6653.54
  Bottom Layer w80: -1274.45,-166.09 J710.3@-1274.45,151.77 J710.3@-1274.45,153.77
  other v1: -4360,3327.64
FAULTN_1: R409.1 U400.18 U801.7 | length 4127.7
  Top Layer w10: v1(-2442,3562) -2390,3562 -2367.74,3584.26 U801.7@-2206.86,3584.26 ; v1@-1656,3114 -1656,2157.28 -1015.97,1517.25 U400.18@-506.62,1517.25 -465.97,1517.25 -455.45,1506.73 -455.45,1482.55 -519.45,1418.55 -519.45,1314.55 -579.27,1254.73 R409.1@-589.45,1254.73
  Bottom Layer w10: v1(-2442,3562) -2442,3272 -2326,3156 -1702,3156 v1(-1656,3110)
FAULTN_2: R509.1 U500.18 U801.45 | length 2280.5
  Top Layer w10: v1(-1876.86,3643.32) U801.45@-1748.04,3643.32 ; v1(-676,4782) -654,4782 -590.75,4845.25 U500.18@-508.62,4845.25
  Top Layer w15: R509.1@-676,4625.28 v1(-676,4782)
  Bottom Layer w10: v1(-1876.86,3643.32) -1650.68,3643.32 -1413.27,3880.73 -1357.27,3880.73 -676,4562 v1(-676,4782)
GND: C110.2 C111.2 C113.1 C114.2 C115.1 C205.1 C400.2 C401.2 C402.2 C403.2 C404.2 C405.2 C408.2 C409.2 C410.2 C411.2 C412.2 C413.2 C414.2 C500.2 C501.2 C502.2 C503.2 C504.2 C505.2 C508.2 C509.2 C510.2 C511.2 C512.2 C513.2 C514.2 C600.1 C601.1 C602.1 C603.1 C604.1 C605.1 C606.1 C607.1 C608.1 C609.1 C610.1 C611.1 C612.2 C613.2 C800.1 C801.2 C802.2 C803.2 C804.2 C807.2 C809.2 C810.2 C811.2 C812.2 C817.2 C818.2 D104.1 J710.2 J800.4 pad.@-223.45,6148.73 pad.@-239.45,3824.73 pad.@-403.45,566.73 pad.@-439.45,2660.73 POWER.7 R101.2 R108.2 R109.1 R110.1 R112.1 R404.1 R405.1 R413.1 R414.1 R415.2 R416.2 R504.1 R505.1 R513.1 R514.1 R515.2 R516.2 R808.2 SW800.2 SW800.5 U205.3 U400.0 U400.5 U400.29 U400.38 U500.0 U500.5 U500.29 U500.38 U600.3 U601.3 U602.7 U603.3 U604.3 U605.3 U606.3 U607.3 U608.3 U609.7 U610.3 U611.3 U612.3 U613.3 U800.4 U801.8 U801.26 U801.43 U801.56 U802.1 U802.10 U802.19 U803.7 U804.4 U901.4 Y800.2 | length 23597.2
  Top Layer w8: v9(-150,4980.36) 134.36,4980.36 ; v5(-84,1798) 18,1900 18,1976 38,1996 v5(80,1996) ; v5(-72,5126) 48,5246 48,5276 ; v5(46,4916) 136,4826 v5@136,4436 ; 48,5256 48,5276 ; v5(106,5546) 68,5546 48,5526 48,5276
  Top Layer w10: v1(-3378,1896) U802.1@-3318,1896 ; U801.56@-1967.61,3779.14 -1967.61,3734.89 -1947.45,3714.73 v1(-1947.45,3684.73) ; U801.26@-1947.92,3325.32 -1947.92,3378.26 -1929.45,3396.73 v1(-1929.45,3424.73) ; v1(-1872.45,3589.73) -1858.24,3603.95 U801.43@-1753.04,3603.95 ; -642,1778 -637.16,1773.16 U400.5@-506.62,1773.16 U400.0@-411.45,1773.16 ; -630,5104 -627.16,5101.16 U500.5@-508.62,5101.16 U500.0@-369.45,5101.16 ; U500.0@-369.45,5002.73 U500.29@-230.27,5002.73 ; U500.0@-369.45,5128.73 -318.28,5179.9 U500.38@-230.27,5179.9 ; v2@-367.45,1825.73 v2@-316.28,1876.9 ; U400.29@-230.23,1674.73 U400.29@-228.27,1674.73 v6(-367.45,1674.73) -367.45,1784.73 -300.28,1851.9 U400.38@-228.27,1851.9 ; v9(-172,1676) 164,1676 288,1552 364,1552 442,1474 442,1210 372,1140 272,1140 208,1204 v5(208,1272) ; v5(-172,5216) -110,5278 -110,5906 44,6060 44,6416 58,6430 v5(74,6430) 90,6430 105,6415 105,6051 -70,5876 -70,5258 v5(-162,5166) ; v5(-158,1878) -158,2310 8,2476 v8(8,2820) 8,2894 26,2912 54,2912 72,2894 v8(72,2820) 72,2470 -110,2288 -110,1936 ; v5(-142,4810) -96,4764 -96,4204 70.55,4037.45 v4(70.55,3670.73) ; v5(-120,1506) -60,1446 -60,938 76,802 76,446 48,418 v8(44,418) 42,418 16,444 16,796 -110,922 v5(-110,1404) ; v5(-110,1882) -110,1936 ; -110,1912.24 -110,1936 ; v5(-106,4840) -44,4778 -44,4224 132,4048 v5(132,3668) ; v5(14,1590) 122,1482 122,1104 128,1098 v5(128,1024) ; v5(64,5048) v5(207.41,5191.41) ; 134.36,4980.36 158,5004 158,5066 v5(244.63,5152.63) ; v5(144,1628) 274,1498 v5(346,1498)
  Top Layer w12: U802.19@-3632.96,1921.59 v1(-3578,1921.59) ; v1(-3396,2116) -3368,2116 -3357.69,2126.31 U802.10@-3318,2126.31 ; U801.8@-2206.86,3564.58 -2121.46,3564.58 -2084.89,3528 v1(-2042,3528)
  Top Layer w15: C409.2@-870,1760 -854,1776 -854,1846 C408.2@-850,1850 -812,1888 -752,1888 -642,1778 ; C509.2@-850,5050 -827,5073 -827,5163 -794,5196 -734,5196 -642,5104 -630,5104
  Top Layer w20: v1(-3568,5016.73) C611.1@-3518.62,5016.73 ; U613.3@-3509.45,5271.73 v1(-3509.45,5340) ; v1(-3358,5016.73) C609.1@-3308.62,5016.73 ; v1(-3341.27,5271.73) U611.3@-3301.72,5271.73 ; v1(-3256.73,4712.73) U804.4@-3172.45,4712.73 ; v1(-3148,5016.73) C607.1@-3098.62,5016.73 ; v1(-3133.55,5271.73) U608.3@-3093.99,5271.73 ; v1(-2928,5016.73) C605.1@-2878.62,5016.73 ; v1(-2925.82,5271.73) U606.3@-2886.27,5271.73 ; v1(-2718,5016.73) C603.1@-2668.62,5016.73 ; v1(-2713.09,5271.73) U604.3@-2673.54,5271.73 ; v1(-2508,5016.73) C601.1@-2458.62,5016.73 ; v1(-2500.36,5271.73) U601.3@-2460.81,5271.73 ; U609.7@-2362.45,4454.73 v1(-2319.45,4454.73) ; v1(-2292.64,5271.73) U612.3@-2253.08,5271.73 ; v1(-2288,5016.73) C610.1@-2238.62,5016.73 ; v1(-2079.91,5271.73) U610.3@-2040.36,5271.73 ; v1(-2078,5016.73) C608.1@-2028.62,5016.73 ; v1(-1868,5016.73) C606.1@-1818.62,5016.73 ; v1(-1867.18,5271.73) U607.3@-1827.63,5271.73 ; U803.7@-1860.45,2604.73 v1(-1817.45,2604.73) ; U205.3@-1859.45,1802.94 v1(-1859.45,1880.14) ; U602.7@-1802.45,4454.73 v1(-1759.45,4454.73) ; v1(-1658,5016.73) C604.1@-1608.62,5016.73 ; v1(-1654.46,5271.73) U605.3@-1614.9,5271.73 ; U800.4@-1551.45,4253.17 v1(-1477.06,4253.17) ; v1(-1438,5016.73) C602.1@-1388.62,5016.73 ; v1(-1436.73,5271.73) U603.3@-1397.18,5271.73 ; v1(-1228,5016.73) C600.1@-1178.62,5016.73 ; v1(-1224,5271.73) U600.3@-1184.45,5271.73
  Top Layer w30: v4(184,1936) 184,1952 212,1980 C400.2@260,1980 ; v4(214.55,5584.73) C500.2@310.55,5584.73
  Top Layer w50: C414.2@-753.45,601.73 -438.45,601.73 C413.2@-403.45,566.73
  Top Layer w100: D104.1@-679.45,1038.73 v3@-569.27,1038.73
  Bottom Layer w10: C818.2@-3511.55,2036.27 v1(-3511.55,2086.45) ; C205.1@-2850,3015.73 -2781.45,3015.73 v1(-2759.45,2993.73) C801.2@-2707.45,2993.73 ; J800.4@-2809.68,2014.32 cw(c-2852.36,1971.65) -2792,1971.65 cw(c-2731.64,1971.65) J800.4@-2774.32,2014.32 ; C800.1@-2804.55,1902.27 -2792,1914.82 J800.4@-2792,2032 ; J800.4@-2802.61,2021.39 cw(c-2828.21,1995.79) -2792,1995.79 cw(c-2755.79,1995.79) J800.4@-2781.39,2021.39 ; C817.2@-2083.45,2827.73 v1(-2083.45,2894.73) ; C811.2@-1929.45,3331.73 v1(-1929.45,3424.73) ; C802.2@-1410.62,4422.73 v1(-1410.62,4467.56) ; R405.1@-199.45,2340.73 R405.1@-199.45,2380.73 ; R504.1@-169.45,5954.73 -169.45,5794.73 -127.45,5752.73 -127.45,5632.73 R515.2@-119.45,5624.73 ; R413.1@-89.45,774.73 -89.45,816.73 R416.2@-41.45,864.73 ; v8(44,418) 44,304 v5(219,129)
  Bottom Layer w12: v1(-1947.45,3684.73) -1947.45,3774.73 C809.2@-1942.45,3779.73 ; v1(-1872.45,3589.73) C810.2@-1822.45,3589.73 ; v1(-1758,3274) C804.2@-1758,3338
  Bottom Layer w20: C807.2@-3256.73,4601.27 v1(-3256.73,4712.73) ; v1(-2646,3582) U901.4@-2646,3619 ; C613.2@-2582.45,4669.73 v1(-2582.45,4753.55) ; C812.2@-2199.22,3528 v1(-1998,3528) ; C612.2@-2022.45,4679.73 v1@-2022.45,4760 ; v1(-1492,4618.44) R101.2@-1405.38,4618.44 ; v1(-1477.06,4253.17) -1440.18,4253.17 R808.2@-1410.62,4282.73
  Bottom Layer w30: R513.1@-167.45,4224.73 -167.45,4308.73 -132.45,4343.73 R516.2@-110.45,4343.73 ; C510.2@70.55,3584.73 v4(70.55,3670.73) ; v4(276,5124.73) C505.2@310.55,5124.73 ; C511.2@480,6790 v4@570,6790 ; C410.2@490,-80 490,-128 532,-170 v1(560,-170) ; C405.2@490.55,3184.73 v4(576.55,3184.73) ; C411.2@500.55,1414.73 v4(500.55,1510.73)
  Bottom Layer w40: R108.2@-4132,1654 C113.1@-4132,1764 -4132,1842 ; R109.1@-4132,1874 -4132,1842 ; v1(-4008,1842) -4132,1842 ; R112.1@-1176,-78 -1166,-68 -1166,36 ; -990,42 -990,-50 C115.1@-970,-70
  Bottom Layer w50: C110.2@-3160,2730 -3120,2730 -3040,2650 -3040,2460 POWER.7@-2990,2410 ; C115.1@-970,-78 C114.2@-854,-78 ; C401.2@-439.45,2660.73 -394.45,2705.73 C504.2@-394.45,2800.73 ; C501.2@-239.45,3824.73 -214.45,3799.73 C404.2@-214.45,3674.73 ; C513.2@-223.45,6148.73 -178.45,6193.73 C514.2@-178.45,6328.73
  other v1: -4060,1842 -1318,3364 -1280,3392 -1278,3678 -1278,3738 -2024,4758
  other v2: -465.45,1238.73 -415.45,1238.73 -365.45,1238.73 -315.45,1238.73 -465.45,1288.73 -415.45,1288.73 -365.45,1288.73 -315.45,1288.73 -265.45,1288.73 -465.45,1338.73 -415.45,1338.73 -365.45,1338.73 -315.45,1338.73 -265.45,1338.73 -367.45,1474.73 -367.45,1524.73 -317.45,1524.73 -417.45,1574.73 -367.45,1574.73 -317.45,1574.73 -417.45,1824.73 -367.45,1824.73 -317.45,1824.73 -417.45,1874.73 -367.45,1874.73 -317.45,1874.73 -367.45,1924.73 -317.45,1924.73 -379.45,1974.73 -329.45,1974.73 -279.45,1974.73 -229.45,1974.73 -379.45,2024.73 -329.45,2024.73 -279.45,2024.73 -229.45,2024.73 -419.45,4590.73 -369.45,4590.73 -319.45,4590.73 -265.45,4590.73 -419.45,4640.73 -369.45,4640.73 -319.45,4640.73 -265.45,4640.73 -215.45,4640.73 -369.45,4690.73 -319.45,4690.73 -319.45,4740.73 -419.45,4777.73 -369.45,4777.73 -419.45,4827.73 -369.45,4827.73 -319.45,4827.73 -419.45,4877.73 -369.45,4877.73 -319.45,4877.73 -419.45,5127.73 -369.45,5127.73 -319.45,5127.73 -419.45,5177.73 -369.45,5177.73 -319.45,5177.73 -419.45,5227.73 -369.45,5227.73 -319.45,5227.73 -375.45,5312.73 -325.45,5312.73 -275.45,5312.73 -225.45,5312.73 -375.45,5362.73 -325.45,5362.73 -275.45,5362.73 -225.45,5362.73 -175.45,5362.73 -375.45,5412.73 -325.45,5412.73 -275.45,5412.73 -225.45,5412.73 -175.45,5412.73 -375.45,5462.73 -325.45,5462.73 -275.45,5462.73 -225.45,5462.73 -175.45,5462.73 -375.45,5512.73 -325.45,5512.73 -275.45,5512.73 -225.45,5512.73 -175.45,5512.73 -375.45,5562.73 -325.45,5562.73 -275.45,5562.73 -225.45,5562.73 -175.45,5562.73
  other v3: -1124,54 -1028,54 -1026,288 -1122,290 -133.45,394.73 -57.45,394.73 -133.45,464.73 -57.45,464.73 -135.45,540.73 -59.45,540.73 -126,662 -50,662 -126,784 -50,784 -550,1038 -618,1038.73 -277.45,2140.73 -377.45,2142.73 -275.45,2236.73 -375.45,2238.73 -277.45,2334.73 -377.45,2336.73 -277.45,2426.73 -377.45,2428.73 -478,3622 -578,3624 -480,3724 -580,3726 -478,3820 -578,3822 -480,3918 -580,3920 -293.45,3982.73 -183.45,3982.73 -393.45,3984.73 -291.45,4078.73 -391.45,4080.73 -293.45,4176.73 -596,4256 -524,4328 -312,5700 -412,5702 -314,5802 -414,5804 -312,5898 -412,5900 -314,5996 -414,5998
  other v4: -1162,152 -988,156 -860.55,1951.27 -860.55,2019.27 -840.55,5269.27 -840.55,5337.27 568,6790
  other v5: 136,4438
  other v6: -417.45,1624.73 -367.45,1624.73 -317.45,1624.73 -417.45,1674.73 -317.45,1674.73 -417.45,1724.73 -367.45,1724.73 -317.45,1724.73 -417.45,1774.73 -367.45,1774.73 -317.45,1774.73 -419.45,4927.73 -369.45,4927.73 -319.45,4927.73 -419.45,4977.73 -369.45,4977.73 -319.45,4977.73 -419.45,5027.73 -369.45,5027.73 -319.45,5027.73 -419.45,5077.73 -369.45,5077.73 -319.45,5077.73
HOLD: R805.2 U800.7 | length 146.1
  Top Layer w10: U800.7@-1331.45,4353.17 v1(-1263.06,4353.17)
  Bottom Layer w10: R805.2@-1340.62,4352.73 -1340.18,4353.17 v1(-1263.06,4353.17)
IN1: D602.2 J700.1 R602.1 R606.1 U600.1 | length 1969.1
  Top Layer w20: R606.1@-1094.45,5661.73 R606.1@-1084.45,5651.73 ; v1(-1084.45,5431.73) U600.1@-1084.45,5511.73 -1084.45,5914.73 -1094.45,5924.73 -1024,5995.18 -1024,6092 -981.27,6134.73 -671.27,6134.73 -414.45,6391.55 -414.45,6464.53 J700.1@-504.45,6554.53 ; J700.1@-504.45,6521.22 cw(c-504.45,6440.81) -447.59,6497.67 ; J700.1@-504.45,6554.53 -471.14,6554.53 ccw(c-390.73,6554.53) -447.59,6497.67 ; J700.1@-504.45,6554.53 -447.59,6497.67
  Bottom Layer w20: v1(-1084.45,5431.73) -1066.5,5449.69 D602.2@-1066.5,5511.73
IN2: D606.2 J700.4 R612.1 R616.1 U603.1 | length 1928.5
  Top Layer w20: R616.1@-1307.18,5661.73 R616.1@-1297.18,5651.73 ; v1(-1297.18,5431.73) U603.1@-1297.18,5511.73 -1297.18,5914.73 R612.1@-1307.18,5924.73 -1250,5981.91 -1250,6124 -1194,6180 -741.18,6180 J700.4@-504.45,6416.73 ; J700.4@-537.76,6416.73 cw(c-618.17,6416.73) -561.31,6359.87 ; -561.31,6359.87 cw(c-504.45,6303.02) -504.45,6383.43 J700.4@-504.45,6416.73 ; -561.31,6359.87 J700.4@-504.45,6416.73
  Bottom Layer w20: v1(-1297.18,5431.73) -1279.22,5449.69 D606.2@-1279.22,5511.73
IN3: D610.2 J701.1 R622.1 R626.1 U605.1 | length 1945.3
  Top Layer w20: R626.1@-1524.9,5661.73 R626.1@-1524.45,5661.73 -1524.68,5661.5 R626.1@-1514.9,5651.73 ; v1(-1514.9,5431.73) U605.1@-1514.9,5511.73 -1514.9,5914.73 R622.1@-1524.9,5924.73 -1468,5981.64 -1468,6125.35 -1368.62,6224.73 -1048.62,6224.73 -919.45,6353.91 -919.45,6462.53 J701.1@-1011.45,6554.53 ; J701.1@-1011.45,6521.22 cw(c-1011.45,6440.81) -954.59,6497.67 ; J701.1@-1011.45,6554.53 -978.14,6554.53 ccw(c-897.73,6554.53) -954.59,6497.67 ; J701.1@-1011.45,6554.53 -954.59,6497.67
  Bottom Layer w20: v1(-1514.9,5431.73) -1496.95,5449.69 D610.2@-1496.95,5511.73
IN4: D614.2 J701.4 R632.1 R636.1 U607.1 | length 1850.8
  Top Layer w20: R636.1@-1737.63,5661.73 R636.1@-1727.63,5651.73 ; v1(-1727.63,5431.73) U607.1@-1727.63,5511.73 -1727.63,5914.73 R632.1@-1737.63,5924.73 -1682,5980.36 -1682,6112 -1633.27,6160.73 -1534.62,6160.73 -1428.62,6266.73 -1161.45,6266.73 J701.4@-1011.45,6416.73 ; J701.4@-1044.76,6416.73 cw(c-1125.17,6416.73) -1068.31,6359.87 ; -1068.31,6359.87 cw(c-1011.45,6303.02) -1011.45,6383.43 J701.4@-1011.45,6416.73 ; -1068.31,6359.87 J701.4@-1011.45,6416.73
  Bottom Layer w20: v1(-1727.63,5431.73) -1709.68,5449.69 -1709.68,5511.73 D614.2@-1714.67,5511.73
IN5: D618.2 J702.1 R642.1 R646.1 U610.1 | length 1858.6
  Top Layer w20: R646.1@-1950.36,5661.73 R646.1@-1940.36,5651.73 ; v1(-1940.36,5431.73) U610.1@-1940.36,5511.73 -1940.36,5914.73 R642.1@-1950.36,5924.73 -1894,5981.09 -1894,6125.35 -1812.62,6206.73 -1592.62,6206.73 -1424.45,6374.91 -1424.45,6460.53 J702.1@-1518.45,6554.53 ; J702.1@-1518.45,6521.22 cw(c-1518.45,6440.81) -1461.59,6497.67 ; J702.1@-1518.45,6554.53 -1485.14,6554.53 ccw(c-1404.73,6554.53) -1461.59,6497.67 ; J702.1@-1518.45,6554.53 -1461.59,6497.67
  Bottom Layer w20: v1(-1940.36,5431.73) -1922.4,5449.69 -1922.4,5511.73 D618.2@-1926.77,5511.73
IN6: D622.2 J702.4 R652.1 R656.1 U612.1 | length 1766
  Top Layer w20: R656.1@-2163.08,5661.73 R656.1@-2153.08,5651.73 ; v1(-2153.08,5431.73) U612.1@-2153.08,5511.73 -2153.08,5914.73 R652.1@-2163.08,5924.73 -2108,5979.82 -2108,6108 -1959.27,6256.73 -1678.45,6256.73 J702.4@-1518.45,6416.73 ; J702.4@-1551.76,6416.73 cw(c-1632.17,6416.73) -1575.31,6359.87 ; -1575.31,6359.87 cw(c-1518.45,6303.02) -1518.45,6383.43 J702.4@-1518.45,6416.73 ; -1575.31,6359.87 J702.4@-1518.45,6416.73
  Bottom Layer w20: v1(-2153.08,5431.73) -2135.13,5449.69 -2135.13,5511.73 D622.2@-2138.88,5511.73
IN7: D603.2 J703.1 R603.1 R607.1 U601.1 | length 1775.1
  Top Layer w20: R607.1@-2370.81,5661.73 R607.1@-2360.81,5651.73 ; v1(-2360.81,5431.73) U601.1@-2360.81,5511.73 -2360.81,5928.81 -2363.77,5931.77 -2314.62,5980.92 -2314.62,6136.73 -2242.62,6208.73 -2094.62,6208.73 -1929.45,6373.91 -1929.45,6458.53 J703.1@-2025.45,6554.53 ; J703.1@-2025.45,6521.22 cw(c-2025.45,6440.81) -1968.59,6497.67 ; J703.1@-2025.45,6554.53 -1992.14,6554.53 ccw(c-1911.73,6554.53) -1968.59,6497.67 ; J703.1@-2025.45,6554.53 -1968.59,6497.67
  Bottom Layer w20: v1(-2360.81,5431.73) -2342.86,5449.69 -2342.86,5511.73 D603.2@-2345.98,5511.73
